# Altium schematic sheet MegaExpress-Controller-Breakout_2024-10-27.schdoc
size 123 x 93 mm
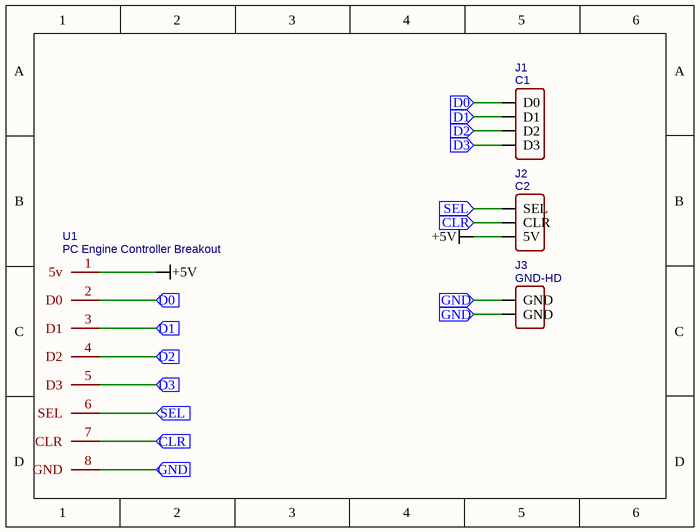
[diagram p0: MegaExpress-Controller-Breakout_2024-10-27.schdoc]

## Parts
J1  C1  [HDR-M-2.54_1X4]
J2  C2  [HDR-M-2.54_1X3]
J3  GND-HD  [HDR-M-2.54_1X2]
U1  PC Engine Controller Breakout  [PC ENGINE CONTROLLER BREAKOUT]

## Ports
CLR (in), D0 (in), D1 (in), D2 (in), D3 (in), GND (in), SEL (in)

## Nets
+5V: J2.3(5V) U1.1(5v)
CLR: J2.2(CLR) U1.7(CLR) ; port CLR
D0: J1.1(D0) U1.2(D0) ; port D0
D1: J1.2(D1) U1.3(D1) ; port D1
D2: J1.3(D2) U1.4(D2) ; port D2
D3: J1.4(D3) U1.5(D3) ; port D3
GND: J3.1(GND) J3.2(GND) U1.8(GND) ; port GND
SEL: J2.1(SEL) U1.6(SEL) ; port SEL

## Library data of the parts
J1 = C1: Contributor: LCEDA_Lib
J2 = C2: Contributor: LCEDA_Lib
J3 = GND-HD: Contributor: LCEDA_Lib
U1 = PC Engine Controller Breakout: Contributor: jonn.blanchard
